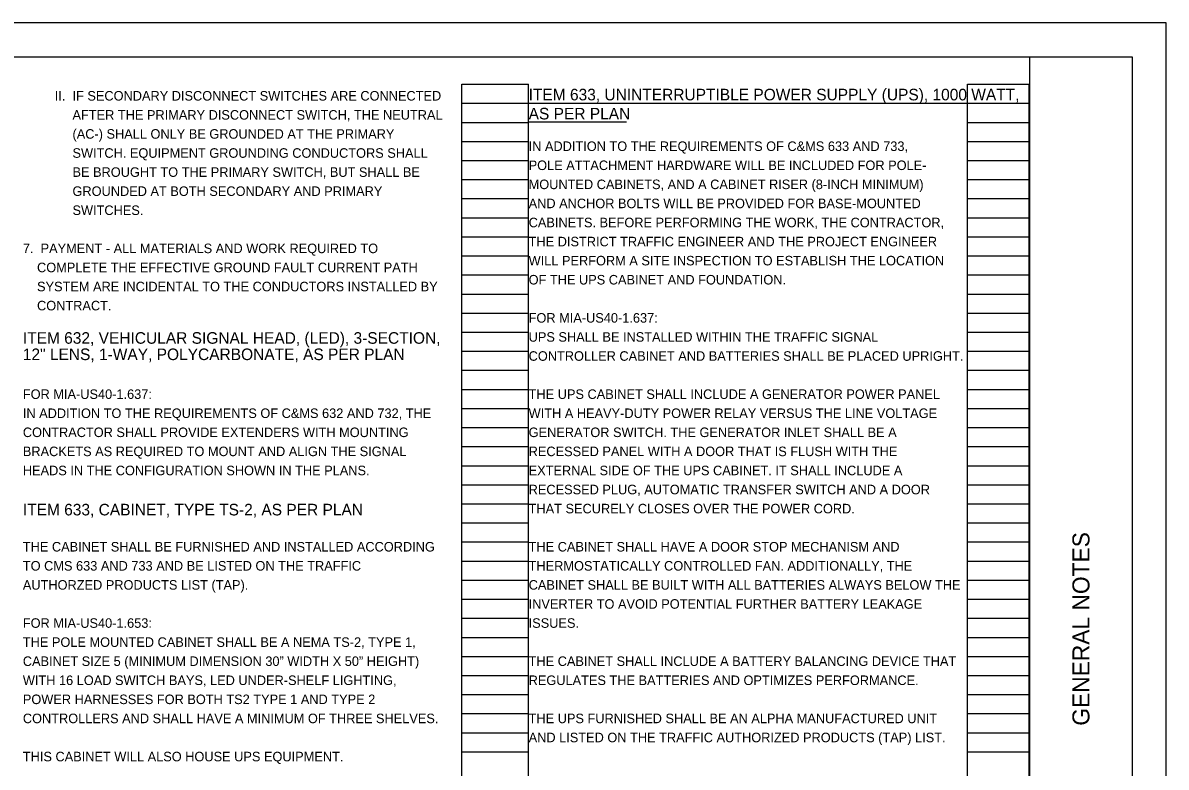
# Model space of a CAD drawing. Extents: x 0 to 34, y -2.4 to 22.
# Drawn here: x 17.24 to 34.01, y 11.11 to 22.04 of the extents above; entities that cross this region are included whole.
import ezdxf

# ---------------------------------------------------------------- set-up
doc = ezdxf.new("R2010")
doc.units = 0
for name, color, linetype in [('SH_Border', 7, 'Continuous'), ('SH_Cut_Line', 7, 'Continuous'), ('SH_Data', 7, 'Continuous'), ('SH_Text', 7, 'Continuous')]:
    doc.layers.add(name, color=color, linetype=linetype)

msp = doc.modelspace()

# ---------------------------------------------------------------- linework, layer by layer
at = {"layer": 'SH_Border'}
msp.add_line((32.012, 0.541), (32.012, 21.541), dxfattribs=at)
msp.add_lwpolyline([(1.512, 21.541), (33.512, 21.541), (33.512, 0.541), (1.512, 0.541)], close=True, dxfattribs=at)
at = {"layer": 'SH_Cut_Line'}
msp.add_lwpolyline([(0.012, 0.041), (34.012, 0.041), (34.012, 22.041), (0.012, 22.041)], close=True, dxfattribs=at)
at = {"layer": 'SH_Data'}
for p, q in [((23.68, 0.98), (23.68, 21.14)), ((23.68, 21.14), (24.66, 21.14)), ((24.66, 0.98), (24.66, 21.14)), ((31.1, 0.98), (31.1, 21.14)), ((31.1, 21.14), (32, 21.14)), ((32, 0.98), (32, 21.14)), ((23.68, 20.86), (24.66, 20.86)), ((31.1, 20.86), (32, 20.86)), ((23.68, 20.58), (24.66, 20.58)), ((31.1, 20.58), (32, 20.58)), ((23.68, 20.3), (24.66, 20.3)), ((31.1, 20.3), (32, 20.3)), ((23.68, 20.02), (24.66, 20.02)), ((31.1, 20.02), (32, 20.02)), ((23.68, 19.74), (24.66, 19.74)), ((31.1, 19.74), (32, 19.74)), ((23.68, 19.46), (24.66, 19.46)), ((31.1, 19.46), (32, 19.46)), ((23.68, 19.18), (24.66, 19.18)), ((31.1, 19.18), (32, 19.18)), ((23.68, 18.9), (24.66, 18.9)), ((31.1, 18.9), (32, 18.9)), ((23.68, 18.62), (24.66, 18.62)), ((31.1, 18.62), (32, 18.62)), ((23.68, 18.34), (24.66, 18.34)), ((31.1, 18.34), (32, 18.34)), ((23.68, 18.06), (24.66, 18.06)), ((31.1, 18.06), (32, 18.06)), ((23.68, 17.78), (24.66, 17.78)), ((31.1, 17.78), (32, 17.78)), ((23.68, 17.5), (24.66, 17.5)), ((31.1, 17.5), (32, 17.5)), ((23.68, 17.22), (24.66, 17.22)), ((31.1, 17.22), (32, 17.22)), ((23.68, 16.94), (24.66, 16.94)), ((31.1, 16.94), (32, 16.94)), ((23.68, 16.66), (24.66, 16.66)), ((31.1, 16.66), (32, 16.66)), ((23.68, 16.38), (24.66, 16.38)), ((31.1, 16.38), (32, 16.38)), ((23.68, 16.1), (24.66, 16.1)), ((31.1, 16.1), (32, 16.1)), ((23.68, 15.82), (24.66, 15.82)), ((31.1, 15.82), (32, 15.82)), ((23.68, 15.54), (24.66, 15.54)), ((31.1, 15.54), (32, 15.54)), ((23.68, 15.26), (24.66, 15.26)), ((31.1, 15.26), (32, 15.26)), ((23.68, 14.98), (24.66, 14.98)), ((31.1, 14.98), (32, 14.98)), ((23.68, 14.7), (24.66, 14.7)), ((31.1, 14.7), (32, 14.7)), ((23.68, 14.42), (24.66, 14.42)), ((31.1, 14.42), (32, 14.42)), ((23.68, 14.14), (24.66, 14.14)), ((31.1, 14.14), (32, 14.14)), ((23.68, 13.86), (24.66, 13.86)), ((31.1, 13.86), (32, 13.86)), ((23.68, 13.58), (24.66, 13.58)), ((31.1, 13.58), (32, 13.58)), ((23.68, 13.3), (24.66, 13.3)), ((31.1, 13.3), (32, 13.3)), ((23.68, 13.02), (24.66, 13.02)), ((31.1, 13.02), (32, 13.02)), ((23.68, 12.74), (24.66, 12.74)), ((31.1, 12.74), (32, 12.74)), ((23.68, 12.46), (24.66, 12.46)), ((31.1, 12.46), (32, 12.46)), ((23.68, 12.18), (24.66, 12.18)), ((31.1, 12.18), (32, 12.18)), ((23.68, 11.9), (24.66, 11.9)), ((31.1, 11.9), (32, 11.9)), ((23.68, 11.62), (24.66, 11.62)), ((31.1, 11.62), (32, 11.62)), ((23.68, 11.34), (24.66, 11.34)), ((31.1, 11.34), (32, 11.34))]:
    msp.add_line(p, q, dxfattribs=at)
at = {"layer": 'SH_Text'}
for p, q in [((24.66, 20.86), (31.774, 20.86)), ((24.66, 20.59), (26.095, 20.59))]:
    msp.add_line(p, q, dxfattribs=at)

# ---------------------------------------------------------------- texts
at = {"layer": 'SH_Data'}
msp.add_text('GENERAL NOTES', height=0.25, rotation=90, dxfattribs=at).set_placement((32.887, 11.723))
at = {"layer": 'SH_Text'}
for s, height, p in [('         II.  IF SECONDARY DISCONNECT SWITCHES ARE CONNECTED', 0.14, (17.24, 20.9)), ('ITEM 633, UNINTERRUPTIBLE POWER SUPPLY (UPS), 1000 WATT,', 0.17, (24.66, 20.903)), ('              AFTER THE PRIMARY DISCONNECT SWITCH, THE NEUTRAL', 0.14, (17.24, 20.62)), ('AS PER PLAN', 0.17, (24.66, 20.623)), ('              (AC-) SHALL ONLY BE GROUNDED AT THE PRIMARY', 0.14, (17.24, 20.34)), ('IN ADDITION TO THE REQUIREMENTS OF C&MS 633 AND 733, ', 0.14, (24.66, 20.16)), ('              SWITCH. EQUIPMENT GROUNDING CONDUCTORS SHALL', 0.14, (17.24, 20.06)), ('POLE ATTACHMENT HARDWARE WILL BE INCLUDED FOR POLE-', 0.14, (24.66, 19.88)), ('              BE BROUGHT TO THE PRIMARY SWITCH, BUT SHALL BE', 0.14, (17.24, 19.78)), ('              GROUNDED AT BOTH SECONDARY AND PRIMARY', 0.14, (17.24, 19.5)), ('MOUNTED CABINETS, AND A CABINET RISER (8-INCH MINIMUM) ', 0.14, (24.66, 19.6)), ('AND ANCHOR BOLTS WILL BE PROVIDED FOR BASE-MOUNTED ', 0.14, (24.66, 19.32)), ('              SWITCHES.', 0.14, (17.24, 19.22)), ('CABINETS. BEFORE PERFORMING THE WORK, THE CONTRACTOR, ', 0.14, (24.66, 19.04)), ('7.  PAYMENT - ALL MATERIALS AND WORK REQUIRED TO', 0.14, (17.24, 18.66)), ('THE DISTRICT TRAFFIC ENGINEER AND THE PROJECT ENGINEER ', 0.14, (24.66, 18.76)), ('WILL PERFORM A SITE INSPECTION TO ESTABLISH THE LOCATION ', 0.14, (24.66, 18.48)), ('    COMPLETE THE EFFECTIVE GROUND FAULT CURRENT PATH', 0.14, (17.24, 18.38)), ('OF THE UPS CABINET AND FOUNDATION.', 0.14, (24.66, 18.2)), ('    SYSTEM ARE INCIDENTAL TO THE CONDUCTORS INSTALLED BY', 0.14, (17.24, 18.1)), ('    CONTRACT.', 0.14, (17.24, 17.82)), ('FOR MIA-US40-1.637:', 0.14, (24.66, 17.64)), ('ITEM 632, VEHICULAR SIGNAL HEAD, (LED), 3-SECTION, ', 0.17, (17.24, 17.33)), ('UPS SHALL BE INSTALLED WITHIN THE TRAFFIC SIGNAL ', 0.14, (24.66, 17.36)), ('12" LENS, 1-WAY, POLYCARBONATE, AS PER PLAN', 0.17, (17.24, 17.09)), ('CONTROLLER CABINET AND BATTERIES SHALL BE PLACED UPRIGHT.', 0.14, (24.66, 17.08)), ('FOR MIA-US40-1.637:', 0.14, (17.24, 16.52)), ('THE UPS CABINET SHALL INCLUDE A GENERATOR POWER PANEL ', 0.14, (24.66, 16.52)), ('IN ADDITION TO THE REQUIREMENTS OF C&MS 632 AND 732, THE ', 0.14, (17.24, 16.24)), ('WITH A HEAVY-DUTY POWER RELAY VERSUS THE LINE VOLTAGE ', 0.14, (24.66, 16.24)), ('CONTRACTOR SHALL PROVIDE EXTENDERS WITH MOUNTING ', 0.14, (17.24, 15.96)), ('GENERATOR SWITCH. THE GENERATOR INLET SHALL BE A ', 0.14, (24.66, 15.96)), ('BRACKETS AS REQUIRED TO MOUNT AND ALIGN THE SIGNAL ', 0.14, (17.24, 15.68)), ('RECESSED PANEL WITH A DOOR THAT IS FLUSH WITH THE ', 0.14, (24.66, 15.68)), ('HEADS IN THE CONFIGURATION SHOWN IN THE PLANS. ', 0.14, (17.24, 15.4)), ('EXTERNAL SIDE OF THE UPS CABINET. IT SHALL INCLUDE A ', 0.14, (24.66, 15.4)), ('RECESSED PLUG, AUTOMATIC TRANSFER SWITCH AND A DOOR ', 0.14, (24.66, 15.12)), ('ITEM 633, CABINET, TYPE TS-2, AS PER PLAN', 0.17, (17.24, 14.81)), ('THAT SECURELY CLOSES OVER THE POWER CORD.', 0.14, (24.66, 14.84)), ('THE CABINET SHALL BE FURNISHED AND INSTALLED ACCORDING ', 0.14, (17.24, 14.28)), ('THE CABINET SHALL HAVE A DOOR STOP MECHANISM AND ', 0.14, (24.66, 14.28)), ('TO CMS 633 AND 733 AND BE LISTED ON THE TRAFFIC ', 0.14, (17.24, 14)), ('THERMOSTATICALLY CONTROLLED FAN. ADDITIONALLY, THE ', 0.14, (24.66, 14)), ('AUTHORZED PRODUCTS LIST (TAP).', 0.14, (17.24, 13.72)), ('CABINET SHALL BE BUILT WITH ALL BATTERIES ALWAYS BELOW THE ', 0.14, (24.66, 13.72)), ('INVERTER TO AVOID POTENTIAL FURTHER BATTERY LEAKAGE ', 0.14, (24.66, 13.44)), ('FOR MIA-US40-1.653:', 0.14, (17.24, 13.16)), ('ISSUES.', 0.14, (24.66, 13.16)), ('THE POLE MOUNTED CABINET SHALL BE A NEMA TS-2, TYPE 1, ', 0.14, (17.24, 12.88)), ('CABINET SIZE 5 (MINIMUM DIMENSION 30” WIDTH X 50” HEIGHT) ', 0.14, (17.24, 12.6)), ('THE CABINET SHALL INCLUDE A BATTERY BALANCING DEVICE THAT ', 0.14, (24.66, 12.6)), ('WITH 16 LOAD SWITCH BAYS, LED UNDER-SHELF LIGHTING, ', 0.14, (17.24, 12.32)), ('REGULATES THE BATTERIES AND OPTIMIZES PERFORMANCE. ', 0.14, (24.66, 12.32)), ('POWER HARNESSES FOR BOTH TS2 TYPE 1 AND TYPE 2 ', 0.14, (17.24, 12.04)), ('CONTROLLERS AND SHALL HAVE A MINIMUM OF THREE SHELVES.', 0.14, (17.24, 11.76)), ('THE UPS FURNISHED SHALL BE AN ALPHA MANUFACTURED UNIT ', 0.14, (24.66, 11.76)), ('AND LISTED ON THE TRAFFIC AUTHORIZED PRODUCTS (TAP) LIST.', 0.14, (24.66, 11.48)), ('THIS CABINET WILL ALSO HOUSE UPS EQUIPMENT.', 0.14, (17.24, 11.2))]:
    msp.add_text(s, height=height, dxfattribs=at).set_placement(p)

doc.saveas('drawing.dxf')
